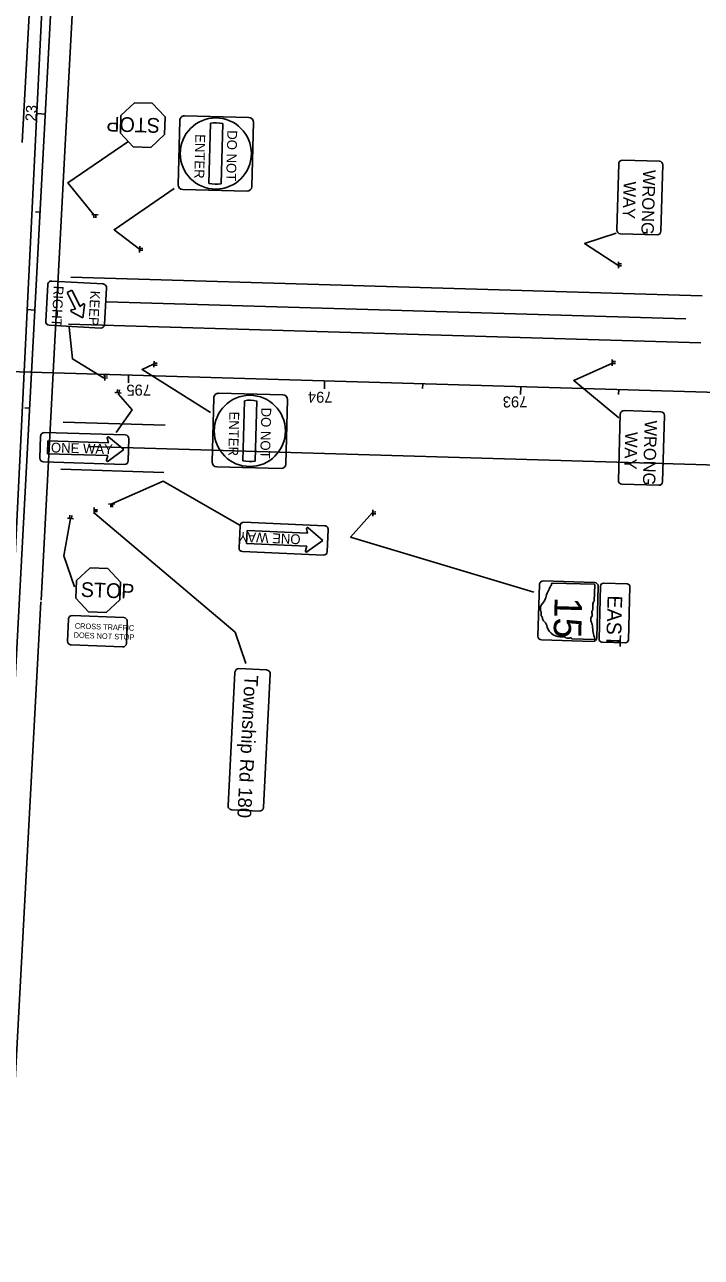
# Model space of a CAD drawing. Extents: x 1658454 to 1663955, y 480219 to 484109.
# Drawn here: x 1661399 to 1661744, y 482260 to 482888 of the extents above; entities that cross this region are included whole.
import ezdxf

# ---------------------------------------------------------------- set-up
doc = ezdxf.new("R2010")
doc.units = 0
for name, color, linetype in [('Default', 7, 'Continuous'), ('PM_P_CL_Double_Solid', 7, 'Continuous'), ('PM_P_Edge_Line', 7, 'Continuous'), ('PM_P_Lane_Line', 7, 'Continuous'), ('PM_X_Lane_Line', 7, 'Continuous'), ('PV_P_EOP', 7, 'Continuous'), ('RW_X_CL_50', 7, 'Continuous'), ('SC_Scratch1', 7, 'Continuous'), ('SN_X_Public', 7, 'Continuous'), ('SN_X_Text', 7, 'Continuous'), ('SV_X_CL_Survey_50', 7, 'Continuous'), ('SV_X_Text', 7, 'Continuous')]:
    doc.layers.add(name, color=color, linetype=linetype)

msp = doc.modelspace()

# ---------------------------------------------------------------- linework, layer by layer
at = {"layer": 'Default'}
for p, q in [((1661409.92, 482842.8), (1661405.93, 482843.01)), ((1661407.25, 482792.87), (1661404.85, 482793)), ((1661404.58, 482742.94), (1661400.58, 482743.15)), ((1661452.34, 482709.84), (1661452.23, 482705.84)), ((1661552.3, 482706.87), (1661552.18, 482702.87)), ((1661602.28, 482705.39), (1661602.21, 482702.99)), ((1661652.26, 482703.9), (1661652.14, 482699.9)), ((1661702.23, 482702.42), (1661702.16, 482700.02)), ((1661401.91, 482693.01), (1661399.51, 482693.14))]:
    msp.add_line(p, q, dxfattribs=at)
at = {"layer": 'PM_P_CL_Double_Solid'}
msp.add_line((1661344.46, 481619.54), (1661462.56, 483826.39), dxfattribs=at)
at = {"layer": 'PM_P_Edge_Line'}
for p, q in [((1661420.1, 482827.05), (1661407.75, 482595.11)), ((1661744.74, 482750.18), (1661423, 482759.73)), ((1661744.02, 482726.19), (1661421.72, 482735.76)), ((1661470.97, 482684.27), (1661419.05, 482685.82)), ((1661470.25, 482660.28), (1661417.76, 482661.84))]:
    msp.add_line(p, q, dxfattribs=at)
at = {"layer": 'PM_P_Lane_Line'}
msp.add_line((1661736.39, 482738.42), (1661441.09, 482747.19), dxfattribs=at)
at = {"layer": 'PM_X_Lane_Line'}
msp.add_line((1662401.15, 482644.65), (1661431.82, 482673.43), dxfattribs=at)
at = {"layer": 'PV_P_EOP'}
for p, q in [((1661398.13, 482828.23), (1661448.64, 483772.06)), ((1661420.1, 482827.05), (1661470.6, 483770.89)), ((1661355.44, 481618.95), (1661407.64, 482594.38))]:
    msp.add_line(p, q, dxfattribs=at)
at = {"layer": 'RW_X_CL_50'}
msp.add_line((1661341.73, 481544.59), (1661467.43, 484100.93), dxfattribs=at)
at = {"layer": 'SC_Scratch1'}
for p, q in [((1661455.41, 482848.55), (1661448.46, 482842.01)), ((1661464.41, 482848.29), (1661455.41, 482848.55)), ((1661470.95, 482841.34), (1661464.41, 482848.29)), ((1661448.2, 482833.01), (1661448.46, 482842.01)), ((1661448.46, 482842.01), (1661448.2, 482833.01)), ((1661448.46, 482842.01), (1661448.2, 482833.01)), ((1661470.69, 482832.34), (1661470.95, 482841.34)), ((1661493.3, 482807.46), (1661494.07, 482838.07)), ((1661500.32, 482837.91), (1661499.55, 482807.3)), ((1661448.2, 482833.01), (1661454.74, 482826.06)), ((1661463.74, 482825.8), (1661470.69, 482832.34)), ((1661454.74, 482826.06), (1661463.74, 482825.8)), ((1661421, 482751.81), (1661423.51, 482753.08)), ((1661425.23, 482743.42), (1661421, 482751.81)), ((1661423.51, 482753.08), (1661427.74, 482744.69)), ((1661423.45, 482743.14), (1661425.23, 482743.42)), ((1661427.74, 482744.69), (1661429.02, 482745.94)), ((1661429.94, 482745.47), (1661429, 482739.05)), ((1661429, 482739.05), (1661423.28, 482742.11)), ((1661510.65, 482666.18), (1661511.42, 482696.79)), ((1661517.67, 482696.63), (1661516.9, 482666.02)), ((1661411.02, 482669.73), (1661411.22, 482676.29)), ((1661411.22, 482676.29), (1661442.04, 482675.37)), ((1661442.04, 482675.37), (1661441.49, 482677.79)), ((1661442.25, 482678.25), (1661449.86, 482671.85)), ((1661441.84, 482668.81), (1661411.02, 482669.73)), ((1661441.15, 482666.44), (1661441.84, 482668.81)), ((1661449.86, 482671.85), (1661441.89, 482665.93)), ((1661512.79, 482630.6), (1661512.5, 482624.04)), ((1661543.59, 482629.23), (1661512.79, 482630.6)), ((1661543.08, 482631.65), (1661543.59, 482629.23)), ((1661551.36, 482625.61), (1661543.85, 482632.1)), ((1661512.5, 482624.04), (1661543.3, 482622.68)), ((1661543.3, 482619.79), (1661551.36, 482625.61)), ((1661543.3, 482622.68), (1661542.58, 482620.31)), ((1661432.76, 482611.73), (1661425.75, 482605.24)), ((1661441.75, 482611.39), (1661432.76, 482611.73)), ((1661448.24, 482604.39), (1661441.75, 482611.39)), ((1661425.75, 482605.24), (1661425.41, 482596.25)), ((1661448.24, 482604.39), (1661447.9, 482595.39)), ((1661447.9, 482595.39), (1661448.24, 482604.39)), ((1661447.9, 482595.39), (1661448.24, 482604.39)), ((1661689.62, 482603.25), (1661668.28, 482603.88)), ((1661689.73, 482594.73), (1661689.98, 482602.96)), ((1661692.16, 482575.4), (1661692.92, 482602.39)), ((1661694.46, 482603.84), (1661706.46, 482603.51)), ((1661707.91, 482601.96), (1661707.16, 482574.97)), ((1661425.41, 482596.25), (1661431.9, 482589.25)), ((1661440.89, 482588.91), (1661447.9, 482595.39)), ((1661431.9, 482589.25), (1661440.89, 482588.91)), ((1661678.52, 482575.44), (1661689.68, 482575.11)), ((1661678.52, 482575.44), (1661678.52, 482575.44)), ((1661705.61, 482573.52), (1661693.62, 482573.85)), ((1661503.09, 482490.45), (1661506.58, 482558.52)), ((1661508.6, 482560.34), (1661522.74, 482559.62)), ((1661524.56, 482557.6), (1661521.07, 482489.52)), ((1661519.05, 482487.71), (1661504.91, 482488.43))]:
    msp.add_line(p, q, dxfattribs=at)
for points in [[(1661478.48, 482839.56), (1661477.66, 482806.75)], [(1661513.68, 482841.02), (1661480.88, 482841.84)], [(1661515.15, 482805.82), (1661515.97, 482838.62)], [(1661434.59, 482791.47), (1661421.34, 482807.68), (1661451.93, 482828.7)], [(1661722.9, 482818.77), (1661704.15, 482819.33)], [(1661702.22, 482817.51), (1661701.22, 482783.78)], [(1661723.71, 482783.11), (1661724.71, 482816.84)], [(1661457.97, 482773.92), (1661444.95, 482783.87), (1661475.53, 482804.88)], [(1661479.94, 482804.35), (1661512.74, 482803.53)], [(1661703.04, 482781.85), (1661721.78, 482781.29)], [(1661410.12, 482737.24), (1661411.18, 482755.96)], [(1661413.16, 482757.72), (1661439.37, 482756.23)], [(1661441.14, 482754.26), (1661440.07, 482735.54)], [(1661438.09, 482733.77), (1661411.89, 482735.26)], [(1661439.65, 482708.5), (1661423.73, 482718.04), (1661422.08, 482734.16)], [(1661465.12, 482715.47), (1661459.25, 482712.65), (1661494.05, 482690.82)], [(1661446.07, 482680.63), (1661454.14, 482692.12), (1661447.06, 482700.34)], [(1661531.03, 482699.74), (1661498.23, 482700.56)], [(1661495.83, 482698.27), (1661495.01, 482665.47)], [(1661532.49, 482664.53), (1661533.32, 482697.34)], [(1661703.01, 482689.9), (1661702.01, 482656.16)], [(1661723.68, 482691.16), (1661704.94, 482691.72)], [(1661724.5, 482655.49), (1661725.5, 482689.23)], [(1661450.7, 482679.34), (1661409.47, 482680.56)], [(1661407.54, 482678.74), (1661407.2, 482667.5)], [(1661452.18, 482666.16), (1661452.52, 482677.41)], [(1661409.02, 482665.57), (1661450.26, 482664.34)], [(1661497.29, 482663.07), (1661530.09, 482662.25)], [(1661508.74, 482633.53), (1661470.01, 482655.87), (1661443.77, 482644.28)], [(1661703.83, 482654.23), (1661722.57, 482653.68)], [(1661424.71, 482601.93), (1661419.29, 482617.78), (1661422.77, 482636.8)], [(1661512.04, 482562.95), (1661506.62, 482578.8), (1661435.07, 482639.27)], [(1661658.86, 482599.19), (1661565.53, 482627.33), (1661576.68, 482639.85)], [(1661508.65, 482621.87), (1661509.15, 482633.11)], [(1661511.1, 482634.9), (1661552.31, 482633.07)], [(1661554.1, 482631.11), (1661553.6, 482619.87)], [(1661551.65, 482618.08), (1661510.44, 482619.91)], [(1661689.93, 482604.16), (1661663.69, 482604.94)], [(1661661.76, 482603.12), (1661660.99, 482576.88)], [(1661690.97, 482575.99), (1661691.75, 482602.23)], [(1661449.88, 482586.34), (1661423.65, 482587.34)], [(1661421.7, 482585.53), (1661421.27, 482574.29)], [(1661451.25, 482573.15), (1661451.68, 482584.39)], [(1661662.8, 482574.95), (1661689.04, 482574.17)], [(1661423.08, 482572.35), (1661449.31, 482571.35)]]:
    msp.add_lwpolyline(points, dxfattribs=at)
for centre in [(1661496.81, 482822.69), (1661514.16, 482681.4)]:
    msp.add_circle(centre, 18.13, dxfattribs=at)
for centre, radius, start, end in [((1661480.82, 482839.5), 2.34, 88.56558, 178.56558), ((1661496.81, 482822.69), 15.62, 77.02862, 100.10254), ((1661513.62, 482838.68), 2.34, 358.56558, 88.56558), ((1661704.1, 482817.45), 1.88, 88.29934, 178.29934), ((1661722.84, 482816.9), 1.88, 358.29934, 88.29934), ((1661480, 482806.7), 2.34, 178.56558, 268.56558), ((1661496.81, 482822.69), 15.62, 257.02862, 280.10254), ((1661512.8, 482805.87), 2.34, 268.56558, 358.56558), ((1661703.1, 482783.72), 1.88, 178.29934, 268.29934), ((1661721.84, 482783.16), 1.88, 268.29934, 358.29934), ((1661413.06, 482755.85), 1.88, 86.7482, 176.7482), ((1661439.26, 482754.36), 1.88, 356.7482, 86.7482), ((1661423.54, 482742.6), 0.548, 99.1104, 241.82744), ((1661429.4, 482745.55), 0.548, 351.66896, 134.386), ((1661411.99, 482737.13), 1.88, 176.7482, 266.7482), ((1661438.2, 482735.64), 1.88, 266.7482, 356.7482), ((1661498.17, 482698.22), 2.34, 88.56558, 178.56558), ((1661530.97, 482697.39), 2.34, 358.56558, 88.56558), ((1661514.16, 482681.4), 15.62, 77.02862, 100.10254), ((1661704.89, 482689.84), 1.88, 88.29934, 178.29934), ((1661723.63, 482689.29), 1.88, 358.29934, 88.29934), ((1661409.41, 482678.69), 1.88, 88.29934, 178.29934), ((1661441.95, 482677.89), 0.471, 49.95732, 192.51673), ((1661450.64, 482677.46), 1.88, 358.29934, 88.29934), ((1661409.08, 482667.44), 1.88, 178.29934, 268.29934), ((1661441.61, 482666.31), 0.471, 164.05613, 306.67187), ((1661450.31, 482666.22), 1.88, 268.29934, 358.29934), ((1661497.35, 482665.41), 2.34, 178.56558, 268.56558), ((1661514.16, 482681.4), 15.62, 257.02862, 280.10254), ((1661530.15, 482664.59), 2.34, 268.56558, 358.56558), ((1661703.88, 482656.11), 1.88, 178.29934, 268.29934), ((1661722.63, 482655.55), 1.88, 268.29934, 358.29934), ((1661511.02, 482633.02), 1.88, 87.45856, 177.45856), ((1661543.54, 482631.74), 0.471, 49.08604, 191.70177), ((1661552.23, 482631.19), 1.88, 357.45856, 87.45856), ((1661510.52, 482621.78), 1.88, 177.45856, 267.45856), ((1661543.03, 482620.17), 0.471, 163.24118, 305.80058), ((1661551.73, 482619.96), 1.88, 267.45856, 357.45856), ((1661663.64, 482603.06), 1.88, 88.29934, 178.29934), ((1661685.86, 482591.05), 21.54, 148.71226, 165.49784), ((1661667.02, 482603.03), 0.905, 298.04772, 1.57109), ((1661670.41, 482603.44), 2.51, 175.63833, 188.9032), ((1661668.23, 482603.56), 0.329, 80.25773, 166.60595), ((1661689.65, 482602.93), 0.326, 6.42944, 96.42944), ((1661689.88, 482602.28), 1.88, 358.29934, 88.29934), ((1661694.42, 482602.34), 1.5, 88.38992, 178.38992), ((1661706.41, 482602.01), 1.5, 358.38992, 88.38992), ((1661666.55, 482590.75), 4.28, 138.99971, 194.59118), ((1661658.52, 482598.28), 6.74, 315.4835, 344.13531), ((1661677.67, 482592.08), 11.35, 348.78603, 3.28761), ((1661692.15, 482592.69), 3.16, 139.91885, 179.41122), ((1661423.58, 482585.46), 1.87, 87.8213, 177.8213), ((1661449.81, 482584.47), 1.87, 357.8213, 87.8213), ((1661659.1, 482588.5), 3.51, 353.99446, 19.50929), ((1661664.87, 482588.02), 2.28, 177.07636, 223.84861), ((1661662.75, 482586.02), 0.641, 334.05107, 40.94776), ((1661690.16, 482585.34), 2.28, 142.15555, 203.12753), ((1661686.85, 482587.89), 1.9, 322.76602, 27.44047), ((1661689.36, 482589.15), 0.912, 128.0914, 205.40171), ((1661665.69, 482586.21), 2.41, 191.17253, 231.57645), ((1661661.61, 482581.15), 4.09, 2.70246, 50.87609), ((1661672.68, 482583.97), 7.46, 200.60823, 277.28518), ((1661682.82, 482581.53), 6, 5.64552, 29.06819), ((1661718.54, 482584.28), 29.83, 184.14381, 197.20579), ((1661423.15, 482574.22), 1.87, 177.8213, 267.8213), ((1661662.86, 482576.82), 1.88, 178.29934, 268.29934), ((1661673.81, 482574.46), 2.12, 45.10584, 95.22893), ((1661676.38, 482578.66), 2.91, 248.3323, 291.94891), ((1661677.7, 482575.54), 0.485, 16.24332, 118.63631), ((1661678.49, 482575.78), 0.335, 197.90315, 276.03347), ((1661689.1, 482576.04), 1.88, 268.29934, 358.29934), ((1661689.74, 482575.42), 0.313, 260.16143, 6.03734), ((1661693.66, 482575.35), 1.5, 178.38992, 268.38992), ((1661705.66, 482575.02), 1.5, 268.38992, 358.38992), ((1661449.38, 482573.22), 1.87, 267.8213, 357.8213), ((1661508.5, 482558.42), 1.92, 87.06499, 177.06499), ((1661522.64, 482557.7), 1.92, 357.06499, 87.06499), ((1661505.01, 482490.35), 1.92, 177.06499, 267.06499), ((1661519.15, 482489.63), 1.92, 267.06499, 357.06499)]:
    msp.add_arc(centre, radius, start, end, dxfattribs=at)
at = {"layer": 'SN_X_Public'}
for p, q in [((1661433.58, 482791.57), (1661436.78, 482791.41)), ((1661434.7, 482791.51), (1661434.62, 482789.92)), ((1661435.18, 482791.49), (1661435.18, 482791.49)), ((1661435.66, 482791.47), (1661435.58, 482789.87)), ((1661457.93, 482772.32), (1661458.01, 482775.52)), ((1661457.99, 482774.4), (1661459.59, 482774.36)), ((1661457.96, 482773.44), (1661459.56, 482773.4)), ((1661457.97, 482773.92), (1661457.97, 482773.92)), ((1661702.01, 482764.36), (1661702.03, 482767.56)), ((1661702.02, 482765.96), (1661702.02, 482765.96)), ((1661702.02, 482765.48), (1661703.62, 482765.47)), ((1661702.03, 482766.44), (1661703.63, 482766.43)), ((1661698.89, 482714.61), (1661698.9, 482717.81)), ((1661465.3, 482713.78), (1661465.38, 482716.98)), ((1661465.33, 482714.9), (1661466.93, 482714.86)), ((1661465.34, 482715.38), (1661465.34, 482715.38)), ((1661465.36, 482715.86), (1661466.95, 482715.82)), ((1661698.89, 482716.21), (1661698.89, 482716.21)), ((1661698.89, 482715.73), (1661700.49, 482715.72)), ((1661698.9, 482716.69), (1661700.5, 482716.68)), ((1661440.22, 482707.13), (1661439.86, 482710.31)), ((1661439.99, 482709.2), (1661441.58, 482709.38)), ((1661440.04, 482708.72), (1661440.04, 482708.72)), ((1661440.09, 482708.25), (1661441.68, 482708.42)), ((1661448.57, 482700.62), (1661445.39, 482701.02)), ((1661446.51, 482700.88), (1661446.7, 482702.46)), ((1661446.98, 482700.82), (1661446.98, 482700.82)), ((1661447.46, 482700.76), (1661447.66, 482702.35)), ((1661434.85, 482639.16), (1661434.83, 482642.36)), ((1661442.12, 482644.15), (1661445.32, 482644.17)), ((1661443.24, 482644.15), (1661443.25, 482642.55)), ((1661443.72, 482644.16), (1661443.72, 482644.16)), ((1661444.2, 482644.16), (1661444.21, 482642.56)), ((1661424.36, 482636.61), (1661421.18, 482636.98)), ((1661422.29, 482636.85), (1661422.48, 482638.44)), ((1661422.77, 482636.8), (1661422.77, 482636.8)), ((1661423.25, 482636.74), (1661423.43, 482638.33)), ((1661434.83, 482641.24), (1661436.43, 482641.25)), ((1661434.84, 482640.76), (1661434.84, 482640.76)), ((1661434.84, 482640.28), (1661436.44, 482640.29)), ((1661576.8, 482638), (1661576.78, 482641.2)), ((1661576.79, 482640.08), (1661578.39, 482640.09)), ((1661576.79, 482639.6), (1661576.79, 482639.6)), ((1661576.79, 482639.12), (1661578.39, 482639.13))]:
    msp.add_line(p, q, dxfattribs=at)
at = {"layer": 'SN_X_Text'}
for points in [[(1661702.32, 482765.5), (1661684.83, 482776.85), (1661700.93, 482782.19)], [(1661702.32, 482688.02), (1661679.3, 482707), (1661698.98, 482715.86)]]:
    msp.add_lwpolyline(points, dxfattribs=at)
at = {"layer": 'SV_X_CL_Survey_50'}
for p, q in [((1661328.12, 481314.2), (1661477.68, 484108.99)), ((1663951.73, 482635.63), (1658453.66, 482798.87))]:
    msp.add_line(p, q, dxfattribs=at)

# ---------------------------------------------------------------- texts
at = {"layer": 'SC_Scratch1'}
for s, height, rotation, p in [('STOP', 7.5, 178.29934, (1661468.49, 482840.66)), ('ENTER', 5, 268.56558, (1661486.43, 482832.59)), ('DO NOT', 5, 268.56558, (1661502.74, 482834.59)), ('WRONG', 6.281, 268.29934, (1661714.69, 482814.46)), ('WAY', 6.281, 268.29934, (1661704.76, 482808.57)), ('RIGHT', 5, 266.7482, (1661414.28, 482755.43)), ('KEEP', 5, 266.7482, (1661432.92, 482752.92)), ('DO NOT', 5, 268.56558, (1661520.09, 482693.31)), ('ENTER', 5, 268.56558, (1661503.78, 482691.31)), ('WRONG', 6.281, 268.29934, (1661715.48, 482686.84)), ('WAY', 6.281, 268.29934, (1661705.55, 482680.95)), ('ONE WAY', 5, 358.29934, (1661412.71, 482670.46)), ('ONE WAY', 5, 177.45856, (1661540.12, 482628.6)), ('STOP', 7.5, 357.8213, (1661427.88, 482596.91)), ('15', 14.063, 268.29934, (1661669.58, 482596.89)), ('EAST', 7.5, 268.38992, (1661696.54, 482597.69)), ('CROSS TRAFFIC', 2.8125, 357.8213, (1661424.91, 482580.72)), ('DOES NOT STOP', 2.8125, 357.8213, (1661424.31, 482576.05)), ('Township Rd 180', 7.0009, 267.06499, (1661511.49, 482557.14))]:
    msp.add_text(s, height=height, rotation=rotation, dxfattribs=at).set_placement(p)
at = {"layer": 'SV_X_Text'}
for s, rotation, p in [('23', 86.93677, (1661405.3, 482838.95)), ('795', 180.53411, (1661463.75, 482705.02)), ('794', 180.53411, (1661556.26, 482701.4)), ('793', 180.53411, (1661655.59, 482699.01))]:
    msp.add_text(s, height=5.6, rotation=rotation, dxfattribs=at).set_placement(p)

doc.saveas('drawing.dxf')
